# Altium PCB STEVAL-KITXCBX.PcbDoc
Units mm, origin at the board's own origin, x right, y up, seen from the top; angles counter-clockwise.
Board outline 62 x 54 mm, 2 copper layers (Top Layer, Bottom Layer), stack 1.543 mm thick; 46 components, 22 nets, 135 pads, 31 vias.
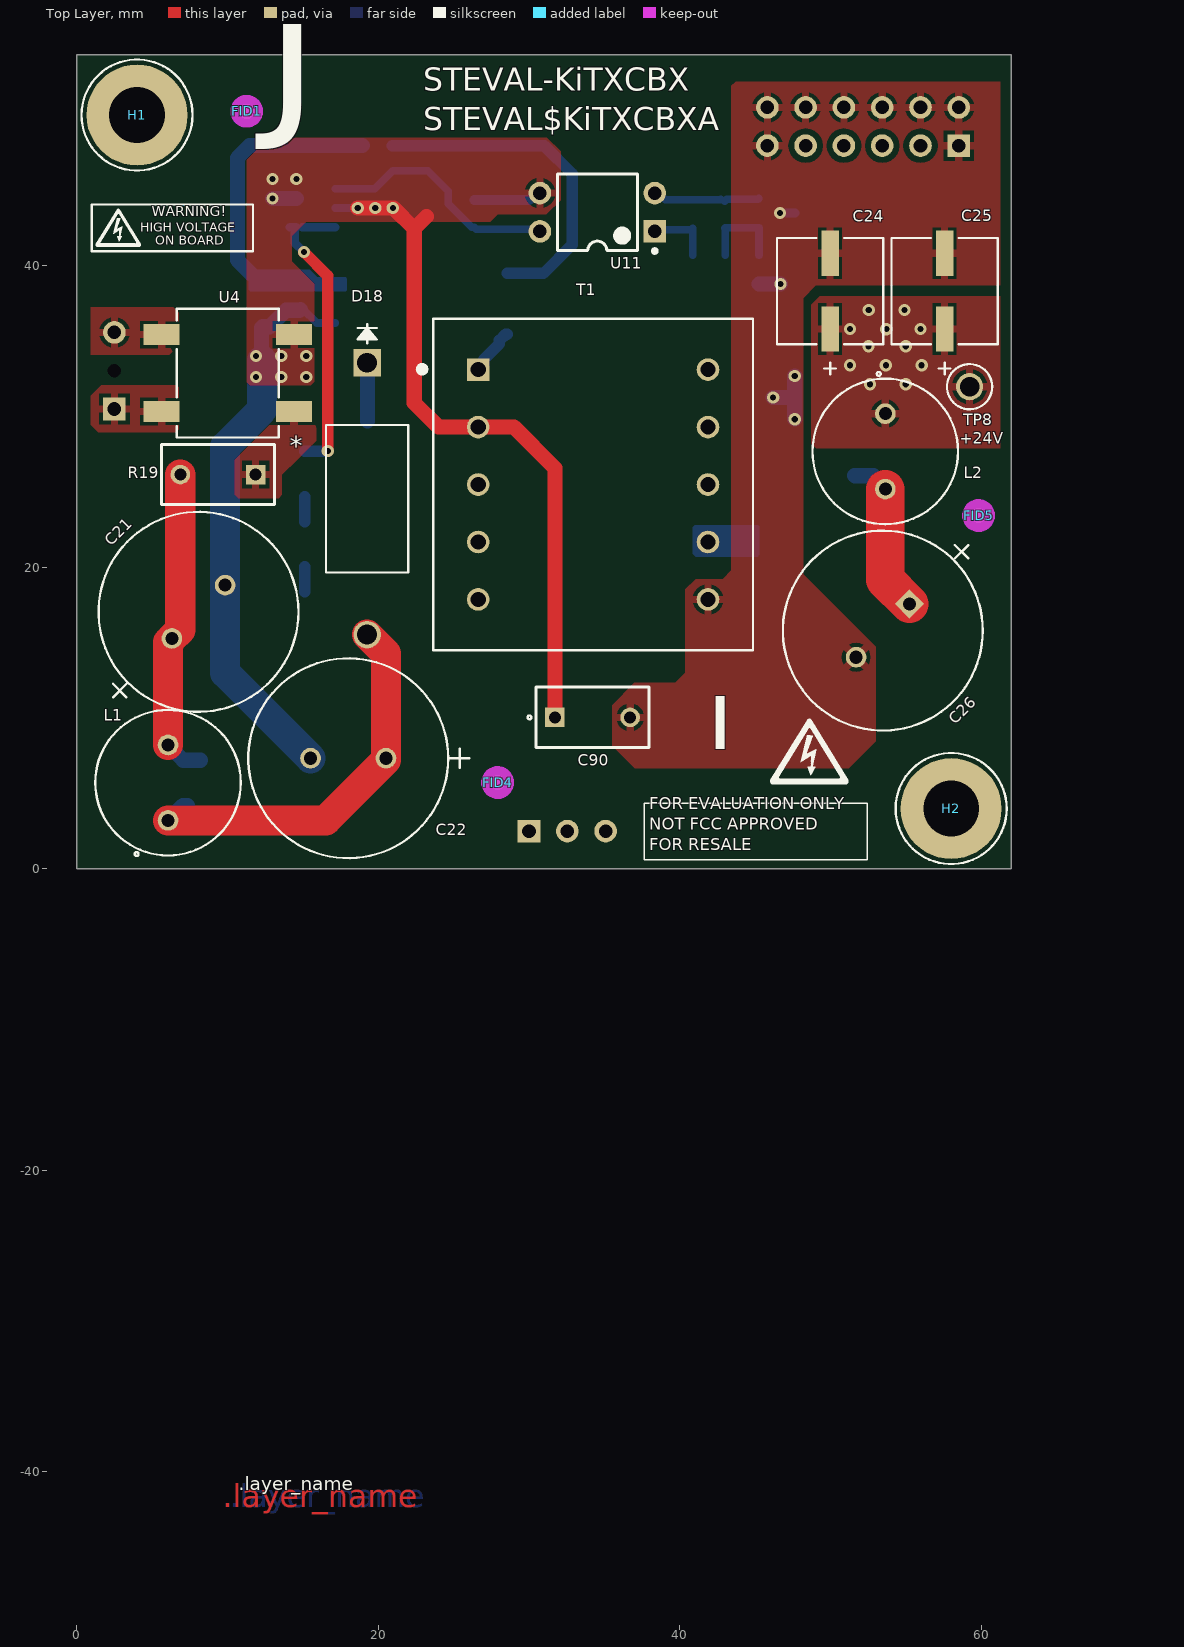
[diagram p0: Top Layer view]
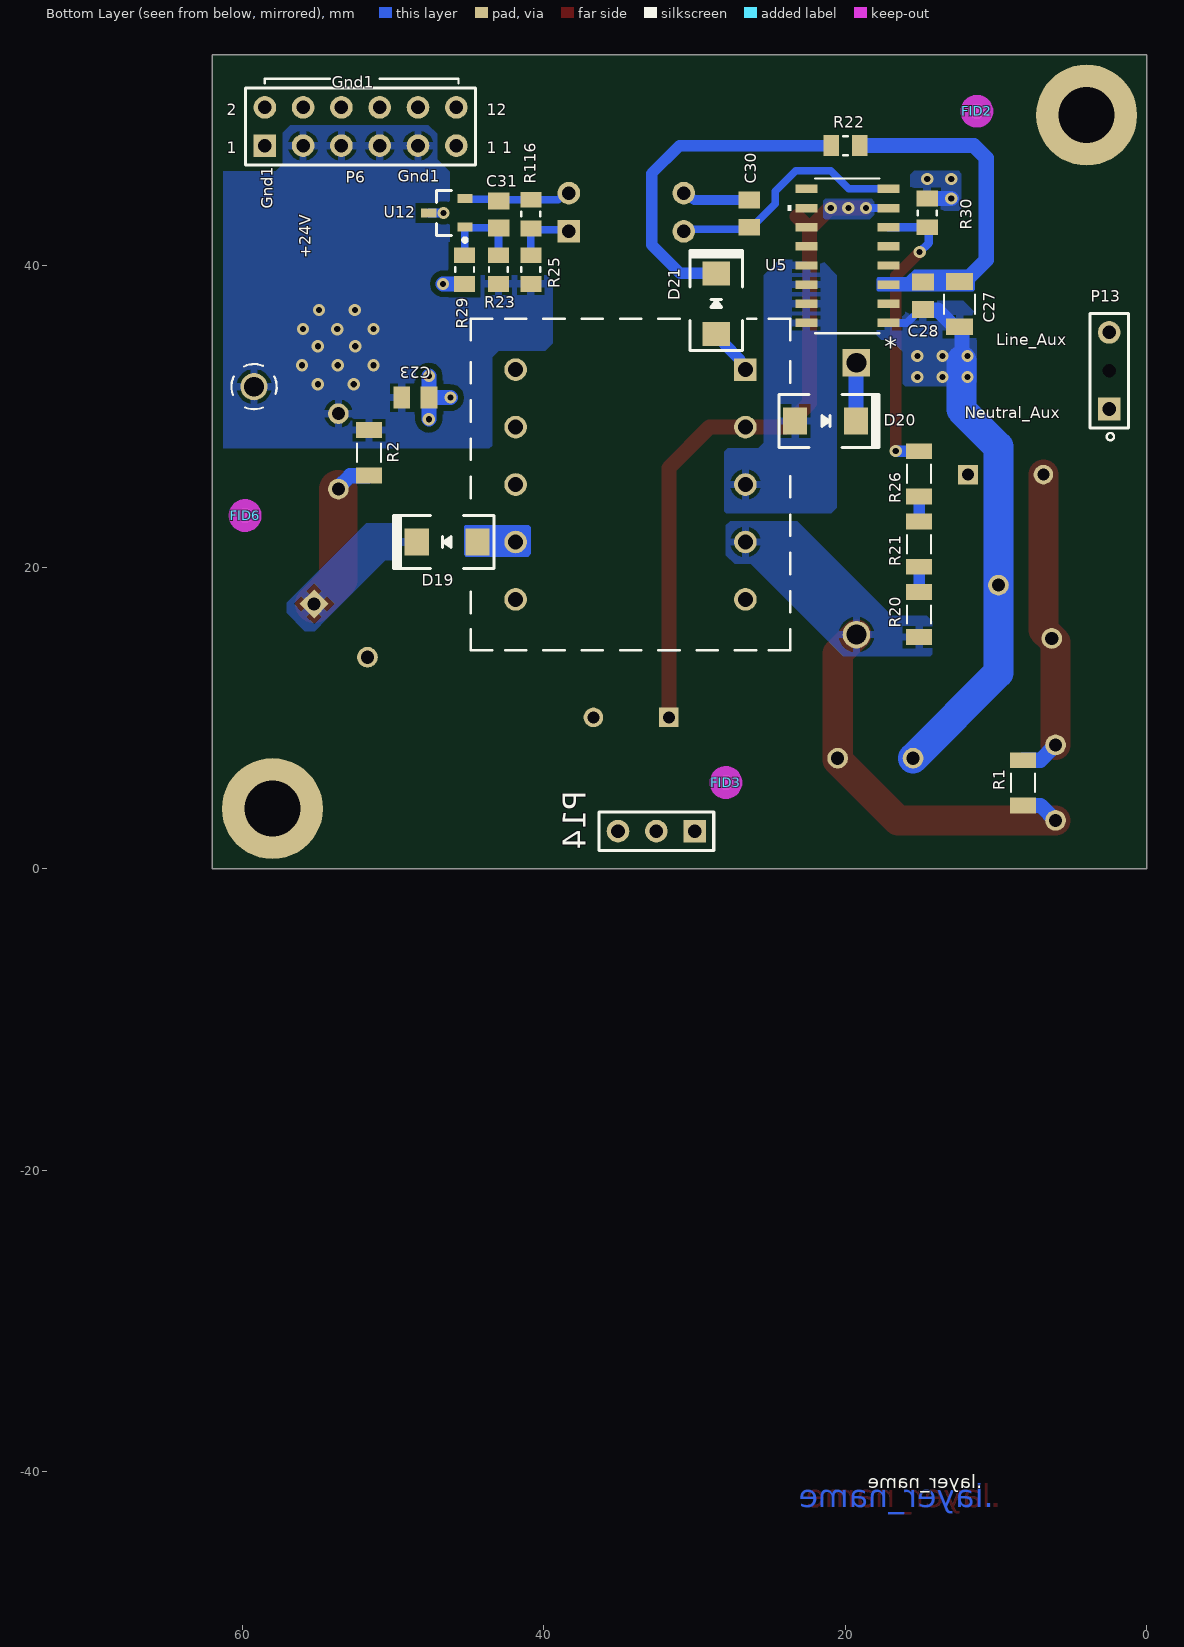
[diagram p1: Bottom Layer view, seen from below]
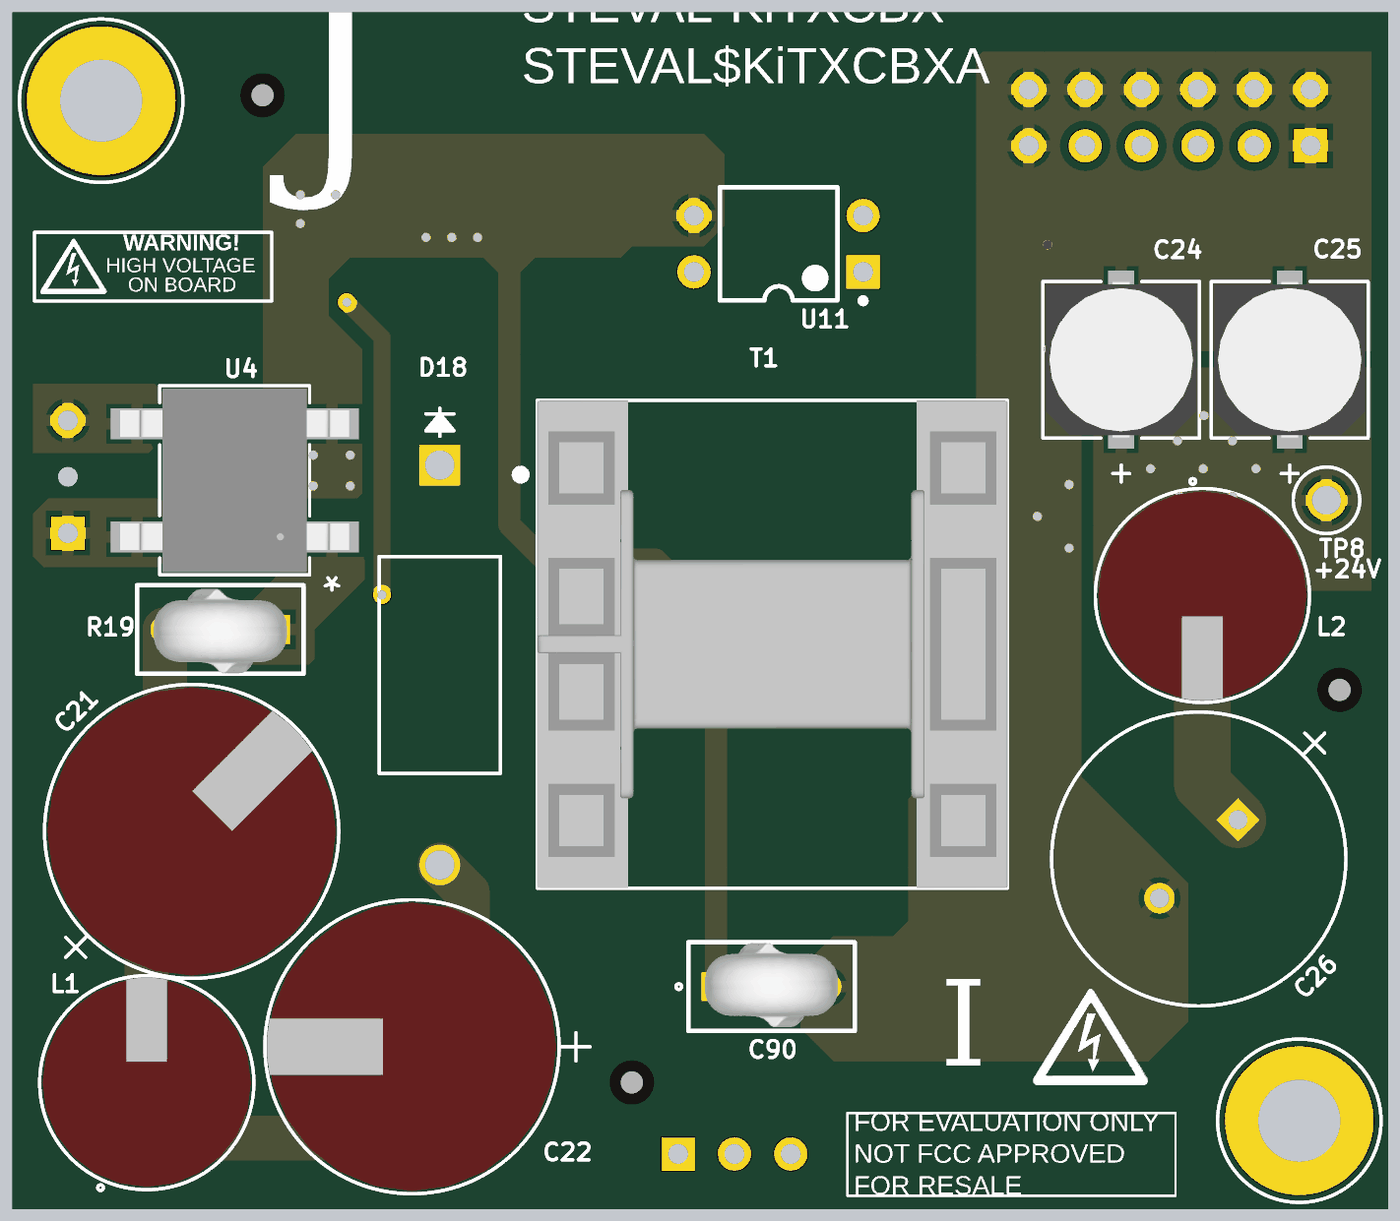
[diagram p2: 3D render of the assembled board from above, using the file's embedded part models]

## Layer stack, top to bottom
Top Solder: solder mask 0.0102, Solder Resist, Dk 3.5
Top Layer: signal copper 0.035
Dielectric: core 1.4732, FR-4 High TG, Dk 4.2
Bottom Layer: signal copper 0.035
Bottom Solder: solder mask 0.0102, Solder Resist, Dk 3.5

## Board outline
0,0 0,54 62,54 62,0

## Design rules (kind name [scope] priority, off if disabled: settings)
AcuteAngle [All] p1: minimum=4.50000000000000E+0001 checktracksonly=FALSE
AssemblyTestPointUsage [All] p1: valid=2
BoardOutlineClearance BoardOutlineClearance_MountingHoles [OnCopper and InComponentClass('Mounting Holes')] p1: gap=1.016 ignorepadtopadclearanceinfootprint=FALSE
BoardOutlineClearance BoardOutlineClearance_Poly [OnCopper and IsPoly] p2: gap=0.737 ignorepadtopadclearanceinfootprint=FALSE
BoardOutlineClearance [OnCopper and Not InComponentClass('Logo') and not InComponentClass('FiducialMark') and not InRegion(1000,500,4000,800) and not InPoly] p3: gap=0.737 ignorepadtopadclearanceinfootprint=FALSE except(0: Text-OutlineEdge; 0.635: SMDPad-OutlineEdge THPad-OutlineEdge)
Clearance Clearance_Keepouts [((IsTrack Or IsArc) And Not InPoly) And IsFree and IsKeepOut vs ((IsTrack Or IsArc) And Not InPoly) And IsFree and IsKeepOut] p1: gap=0 ignorepadtopadclearanceinfootprint=FALSE
Clearance Clearance_FiducialMark [IsKeepOut and InComponentClass('FiducialMark') vs IsPad and InComponentClass('FiducialMark')] p2: gap=0 ignorepadtopadclearanceinfootprint=FALSE
Clearance [All] p3: gap=0.229 ignorepadtopadclearanceinfootprint=TRUE except(0: Arc-SMDPad; 0.381: Arc-Poly Track-Poly SMDPad-Poly THPad-Poly Via-Poly Fill-Poly Fill-Region Poly-Region Region-Region; 0.508: Poly-Poly)
DiffPairsRouting [All] p1: maxlimit=2.54 minlimit=0.254 mostfreqgap=0.254 toplayer_minwidth=0.381 toplayer_maxwidth=0.381 toplayer_prefwidth=0.381 bottomlayer_minwidth=0.381 bottomlayer_maxwidth=0.381 bottomlayer_prefwidth=0.381 maxuncoupledlength=25.4
FabricationTestPointUsage TestPointUsage [All] p1: valid=2 allowmultiple=FALSE
FabricationTestpoint Testpoint [All] p1: side=3 testpointundercomponent=TRUE minsize=1.016 maxsize=2.54 preferedsize=1.524 minholesize=0 maxholesize=1.016 preferedholesize=0.813 testpointgrid=0.025 allowsidetop=TRUE allowsidebottom=TRUE usegrid=TRUE gridtolerance=0
FanoutControl Fanout_LCC [IsLCC] p1: bgadir=Out bgaviamode=Centered fanoutstyle=Auto fanoutdirection=Alternating viagrid=0.025 // Fanout_LCC (Default Rule)
FanoutControl Fanout_BGA [IsBGA] p2: bgadir=Out bgaviamode=Centered fanoutstyle=Auto fanoutdirection=Alternating viagrid=0.025 // Fanout_BGA (Default Rule)
FanoutControl Fanout_Default [All] p4: bgadir=Out bgaviamode=Centered fanoutstyle=Auto fanoutdirection=Alternating viagrid=0.025 // Fanout_Default (Default Rule)
FanoutControl Fanout_Small [(CompPinCount < 5)] p5: bgadir=Out bgaviamode=Centered fanoutstyle=Auto fanoutdirection=OutThenIn viagrid=0.025 // Fanout_Small (Default Rule)
HoleSize [All] p1: absolutevalues=TRUE maxlimit=6.375 minlimit=0.2 maxpercent=80.000 minpercent=20.000
HoleToHoleClearance [All] p1: gap=0.2 allowstackedmicrovias=TRUE
MinimumAnnularRing MinimumAnnularRing_ThermalPadVias [IsVia and InAnyComponent] p1: minimumring=0.15
MinimumAnnularRing [All] p2: minimumring=0.127
MinimumSolderMaskSliver MinimumSolderMaskSliver_Logo [InComponentClass('Logo') vs InComponentClass('Logo')] p1: minsoldermaskwidth=0.018
MinimumSolderMaskSliver [All] p2: minsoldermaskwidth=0.076
PlaneConnect [All] p1: planeconnectstyle=Relief reliefexpansion=0.254 reliefentries=4 reliefconductorwidth=0.254 reliefairgap=0.254
PolygonConnect [All] p1: thpad.connectstyle=Relief thpad.reliefconductorwidth=0.508 thpad.reliefentries=4 thpad.polygonreliefangle="90 Angle" thpad.airgapwidth=0.254 smdpad.connectstyle=Relief smdpad.reliefconductorwidth=0.508 smdpad.reliefentries=4 smdpad.polygonreliefangle="90 Angle" smdpad.airgapwidth=0.2 via.connectstyle=Direct via.reliefconductorwidth=0.254 via.reliefentries=4 via.polygonreliefangle="90 Angle" via.airgapwidth=0.254
RoutingVias ThermalPadVias [IsVia and InAnyComponent] p1: holewidth=0.2 width=0.5 viastyle="Through Hole" minholewidth=0.2 minwidth=0.5 maxholewidth=0.33 maxwidth=0.6
RoutingVias [All] p2: holewidth=0.305 width=0.61 viastyle="Through Hole" minholewidth=0.406 minwidth=0.813 maxholewidth=0.406 maxwidth=0.914
SilkToBoardRegionClearance [Not ((IsComment or IsDesignator) And (Hide <> 'False')) and not InRegion(1000,500,4000,800)] p1:
SilkToSilkClearance SilkToSilkClearance_Pb-FreeLogo [(HasFootprint('Pb-Free_Overlay_Medium') OR HasFootprint('Pb-Free_Overlay_Small')) vs (HasFootprint('Pb-Free_Overlay_Medium') OR HasFootprint('Pb-Free_Overlay_Small'))] p1: silktosilkclearance=0
SilkToSilkClearance [All] p2: silktosilkclearance=0.003
SilkToSolderMaskClearance SilkToComponentPadClearance [(IsPad or IsFill or IsRegion) and InAnycomponent] p1: minsilkscreentomaskgap=0.025 clearancetoexposedcopper=TRUE
SilkToSolderMaskClearance "Silk to Solder Mask Opening" [All] p2: minsilkscreentomaskgap=0 clearancetoexposedcopper=FALSE
SolderMaskExpansion [All] p1: expansion=0.05 istentingtop=FALSE
UnRoutedNet [All] p1: checkbadconnections=TRUE
Width [All] p1: maxlimit=2.54 minlimit=0.152 preferedwidth=0.254 checkconnectedcopper=TRUE
14 further rules are at their usual default settings.

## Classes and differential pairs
component class "D-Aux. Power Supply": C21 C22 C23 C24 C25 C26 C27 C28 C30 C31 C90 CR1 D19 D20 D21 H1 H2 L1 L2 P6 P13 P14 R1 R2 R19 R20 R21 R22 R23 R25 R26 R29 R30 R116 T1 TP8 U4 U5 U11 U12

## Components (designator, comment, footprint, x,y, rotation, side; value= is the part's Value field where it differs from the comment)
C21 "22µF/450 V" CAP_BX_12P5x20_RUB 6.31,15.281 r45 top
C22 "22µF/450 V" CAP_BX_12P5x20_RUB 20.508,7.337 r180 top
C23 "100nF" CAP_0805J_AVX 48.525,31.258 r0 bottom
C24 "22uF" PCAP_EEHZ_D_PAN 49.973,38.319 r90 top
C25 "22uF" PCAP_EEHZ_D_PAN 57.567,38.319 r90 top
C26 "220uF" CAP_2135_12.5X20_VIS 55.235,17.572 r225 top
C27 "10uF/50V" CAP_X7R_1206_AVX 12.431,37.455 r90 bottom
C28 "100nF" CAP_0805J_AVX 14.844,38.014 r90 bottom
C30 "1nF" CAP_0805J_AVX 26.376,43.462 r270 bottom
C31 "47nF" CAP_0805J_AVX 42.992,43.399 r270 bottom
C90 "1nF" Vishay_S102K29Y5PN6TJ5R_0 34.21,10.048 r0 top
D18 "1.5KE300A" DO-201_DIO 19.264,33.569 r270 top
D19 "STTH1R02A" DO214AC-SMA 46.417,21.682 r0 bottom
D20 "STTH1L06A" DO214AC-SMA 21.313,29.708 r180 bottom
D21 "STPS1L60A" DO214AC-SMA 28.56,37.48 r90 bottom
FID1 "Fiducial" Fiducial10-20 11.276,50.248 r0 top
FID2 "Fiducial" Fiducial10-20 11.276,50.248 r180 bottom
FID3 "Fiducial" Fiducial10-20 27.918,5.726 r180 bottom
FID4 "Fiducial" Fiducial10-20 27.918,5.726 r0 top
FID5 "Fiducial" Fiducial10-20 59.815,23.432 r0 top
FID6 "Fiducial" Fiducial10-20 59.815,23.432 r180 bottom
H1 "Hole" HOLE_M3#1 4,50 r0 top
H2 "Hole" HOLE_M3#2 58,4 r0 top
L1 "RLB0914-102KL" IND_RFB0810 6.056,3.216 r90 top
L2 "2.2uH" IND_RFB0810 53.63,30.191 r270 top
P6 "SSW-106-01-G-D" HDR2X6 58.507,47.968 r180 bottom
P13 "SSW-103-01-G-S" HDR1X3#1 2.5,30.5 r90 bottom
P14 "SSW-103-01-G-S" HDR1X3#2 30,2.5 r0 bottom
R1 "NM" RC1206 8.215,5.705 r270 bottom
R2 "NM" RC1206 51.598,27.598 r90 bottom
R19 "B57153S0479M000" R? 11.869,26.152 r180 top
R20 "2M" RC1206 15.115,16.872 r270 bottom
R21 "2M" RC1206 15.115,21.534 r270 bottom
R22 "10" RC0805 19.99,47.968 r0 bottom
R23 "220k" RC0805 43.018,39.75 r270 bottom
R25 "390" RC0805 40.864,39.75 r270 bottom
R26 "2M" RC1206 15.115,26.196 r270 bottom
R29 "12k" RC0805 45.255,39.75 r90 bottom
R30 "62k" RC0805 14.565,43.51 r270 bottom
R116 "1.8k" RC0805 40.864,43.434 r270 bottom
T1 "AD1914-AL" TDK_B66206B1110T001 34.25,25.492 r0 top
TP8 "+24V" TP_20-2136 59.223,31.982 r180 top value="Test Point"
U4 "DF08S-E3/77" SO4_DFS_VIS 10.018,32.883 r180 top
U5 "VIPER318LDTR" SO_18HDTR_STM 19.867,40.655 r0 bottom
U11 "SFH610A-4" DIP-4 34.529,43.551 r180 top
U12 "TS3431BILT" SOT95P245X112-3N 46.433,43.51 r0 bottom

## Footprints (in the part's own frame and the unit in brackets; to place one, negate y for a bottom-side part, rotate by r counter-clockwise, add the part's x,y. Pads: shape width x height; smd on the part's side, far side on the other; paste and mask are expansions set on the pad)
CAP_0805J_AVX [mil]
  rect 44x57 smd paste+0 mask+0: 1(-35.5,0) 2(35.5,0)
  body extent 0,0 10,10, height 10
CAP_2135_12.5X20_VIS [mil]
  rect 54x54 hole 34 mask+0: 1(0,0)
  round 54 hole 34 mask+0: 2(196.85,0)
  silkscreen extent -218,-261 359,261, body extent 0,0 10,10, height 10
CAP_BX_12P5x20_RUB [mil]
  round 54 hole 34 mask+0: 1(0,0) 2(196.85,0)
  silkscreen extent -218,-261 359,261, body extent -158,-256 356,256, height 867
CAP_X7R_1206_AVX [mil]
  rect 44x71 smd paste+0 mask+0: 1(-59,0) 2(59,0)
  silkscreen extent -25,-40 25,40, body extent 0,0 10,10, height 10
DIP-4 [mm] "DIP; 4 Leads; Row Spacing 7.62 mm; Pitch 2.54 mm"
  rect 1.5x1.5 hole 0.9: 1(-3.81,1.27)
  round 1.5 hole 0.9: 2(-3.81,-1.27) 3(3.81,-1.27) 4(3.81,1.27)
  silkscreen extent -3.93,-2.55 2.65,2.69, body extent -3.15,-2.5 3.15,2.5, height 5.6
DO214AC-SMA [mm]
  rect 1.6x1.8 smd paste+0 mask+0.102: 1(-2.015,0) 2(2.015,0)
  silkscreen extent -3.1,-1.75 3.55,1.75, body extent -2.58,-1.3 2.5,1.28, height 2.65
DO-201_DIO [mil]
  rect 72x72 hole 52 mask+0: 1(0,0)
  round 72 hole 52 mask+0: 2(710,0)
  silkscreen extent -101,-108 548,108, body extent 0,0 10,10, height 10
Fiducial10-20 [mm]
  round 1 smd mask+0.5: 1(0,0)
  Top Layer keep-out circle w1.178: c0,0 r0.5
HDR1X3#1 [mm] "Connector; Header; 3 Position"
  rect 1.5x1.5 hole 0.9: 1(0,0)
  round 0 hole 0.9 unplated mask+0.127: 2(2.54,0)
  round 1.5 hole 0.9: 3(5.08,0)
  silkscreen extent -1.27,-1.27 6.35,1.27
HDR1X3#2 [mm] "Connector; Header; 3 Position"
  rect 1.5x1.5 hole 0.9: 1(0,0)
  round 1.5 hole 0.9: 2(2.54,0) 3(5.08,0)
  silkscreen extent -1.27,-1.27 6.35,1.27
HDR2X6 [mm] "Connector; Header; 6x2 Position"
  rect 1.5x1.5 hole 0.9: 1(0,0)
  round 1.5 hole 0.9: 2(0,2.54) 3(2.54,0) 4(2.54,2.54) 5(5.08,0) 6(5.08,2.54) 7(7.62,0) 8(7.62,2.54) 9(10.16,0) 10(10.16,2.54) 11(12.7,0) 12(12.7,2.54)
  silkscreen extent -1.27,-1.27 13.97,3.81
HOLE_M3#1 [mm]
  round 0 all layers, no hole mask+0: 1(-2.25,0) 1(-1.125,-1.949) 1(-1.125,1.949) 1(1.125,-1.949) 1(1.125,1.949) 1(2.25,0)
  round 6.7 hole 3.7 mask+0.1: 1(0,0)
  silkscreen extent -3.68,-3.68 3.68,3.68
HOLE_M3#2 [mm]
  round 0 all layers, no hole: 1(-2.25,0) 1(-1.125,-1.949) 1(-1.125,1.949) 1(1.125,-1.949) 1(1.125,1.949) 1(2.25,0)
  round 6.7 hole 3.7: 1(0,0)
  silkscreen extent -3.68,-3.68 3.68,3.68
IND_RFB0810 [mil]
  round 54 hole 34 mask+0: 1(0,0) 2(197,0)
  silkscreen extent -92,-190 288,190, body extent -86,-185 285,185, height 451
PCAP_EEHZ_D_PAN [mil]
  rect 118x46 smd paste+0 mask+0: 1(-99,0) 2(99,0)
  silkscreen extent -217,-139 139,139, body extent -138,-134 138,134, height 242
R? [mm]
  rect 1.3x1.3 hole 0.8 paste-1000 mask+0: 1(0,0)
  round 1.3 hole 0.8 paste-1000 mask+0: 2(5,0)
  silkscreen extent -1.25,-2 6.25,2, body extent -1.35,-2.1 6.35,2.1, height 0.25
RC0805 [mm]
  rect 1.05x1.4 smd: 1(-0.95,0) 2(0.95,0)
  silkscreen extent -0.15,-0.63 0.15,0.63, body extent -1,-0.63 1,0.63, height 0.84
RC1206 [mm] "RES, SMD, 1.2K OHM,  5%, 1/4W, 1206"
  rect 1.05x1.75 smd: 1(-1.5,0) 2(1.5,0)
  silkscreen extent -0.6,-0.8 0.6,0.8, body extent -1.6,-0.8 1.6,0.8, height 0.84
SO4_DFS_VIS [mm]
  rect 2.4x1.4 smd paste+0 mask+0: 1(-4.394,2.55) 2(-4.394,-2.55) 3(4.394,-2.55) 4(4.394,2.55)
  silkscreen extent -3.38,-4.27 3.38,4.27, body extent -5.16,-4.14 5.16,4.14, height 2.92
SO_18HDTR_STM [mil]
  rect 57.55x22 smd paste+0 mask+0: 1(-107.27,175) 2(-107.27,125) 3(-107.27,75) 4(-107.27,25) 5(-107.27,-25) 6(-107.27,-75) 7(-107.27,-125) 8(-107.27,-175) 9(107.27,-175) 10(107.27,-125) 11(107.27,-75) 12(107.27,-25) 13(107.27,25) 14(107.27,75) 15(107.27,125) 16(107.27,175)
  silkscreen extent -84,-202 156,202, body extent 0,0 10,10, height 10
SOT95P245X112-3N [mm] "SOT23, 3-Leads, Body 2.92x2.45mm, Pitch 0.95mm, IPC Medium Density"
  rect 1x0.6 smd: 1(-1.2,0.95) 2(-1.2,-0.95) 3(1.2,0)
  silkscreen extent -1.32,-1.5 0.7,1.92, body extent -1.3,-1.52 1.3,1.52, height 1.12
TDK_B66206B1110T001 [mm] "BOBBIN COIL FORMER, E 20/10/6 , 10 POS, TH"
  rect 1.5x1.5 / inner round 1.5 / far side rect 1.5x1.5 hole 1: 1(-7.62,7.62)
  round 1.5 hole 1: 2(-7.62,3.81) 3(-7.62,0) 4(-7.62,-3.81) 5(-7.62,-7.62) 6(7.62,-7.62) 7(7.62,-3.81) 8(7.62,0) 9(7.62,3.81) 10(7.62,7.62)
  silkscreen extent -11.75,-11 10.6,11, body extent -10.6,-11 10.6,11, height 16.65
TP_20-2136 [mm] "TEST POINT, BLACK, TH"
  round 1.8 hole 1.3: 1(0,0)
  silkscreen extent -1.5,-1.5 1.5,1.5, body extent -1.49,-1.5 1.5,1.5, height 5.4
Vishay_S102K29Y5PN6TJ5R_0 [mm]
  rect 1.3x1.3 hole 0.8 paste-1000 mask+0: 1(-2.5,0)
  round 1.3 hole 0.8 paste-1000 mask+0: 2(2.5,0)
  silkscreen extent -3.75,-2 3.75,2, body extent -3.85,-2.1 3.85,2.1, height 0.25

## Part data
C21 C22: library part 450BXF22M12.5X20, "22 µF 450 V Aluminum Electrolytic Capacitors Radial, Can - 10000 Hrs @ 105°C", Manufacturer_Part_Number=EKXN451ELL220MK16S, Mfr_Name=Rubycon
C23 C28 C30 C31: library part 08051A561JAT2A, "No Description Available"
C24: library part EEHZA1H220P, "Cap Aluminum 22uF 50V 20% (6.3 X 5.8mm) SMD 0.08 Ohm 1100mA 5000 hr 105°C Embossed T/R", Manufacturer_Part_Number=50PEV22M6.3X6.1, Mfr_Name=Rubycon
C25: library part EEHZA1H220P, "No Description Available", Manufacturer_Part_Number=50PEV22M6.3X6.1, Mfr_Name=Rubycon
C26: library part MAL213668221E3, "No Description Available", Manufacturer_Part_Number=URZ1J221MHD1TO, Mfr_Name=Vishay
C27: library part 12061C104KAT2A, "No Description Available"
C90: library part S102K29Y5PN6TJ5R, "Cap Ceramic 0.001uF 1000V Y5P 10% (7.5 X 4mm) Radial 5mm 85°C T/R", Supplier Part Number 1=810-CK45-B3AD102KYVN
D18: library part 1.5KE300A-T, "Transient Voltage Suppressor diode, D5.4x7.5, 285.00V .. 315.00V, 1500W", Manufacturer 1=STMicroelectronics, Supplier Part Number 1=9884947
D19: library part "Diode Schottky STPS1150A", "Schottky Rectifier Diode", Average Rectified Current=1A, Case/Package=SMA, Forward Voltage=890mV, Manufacturer 2=STMicroelectronics, Manufacturer Part Number 2=STPS1150A, Max Forward Surge Current (Ifsm)=50A, Max Operating Temperature=175°C, Max Repetitive Reverse Voltage (Vrrm)=150V, Max Reverse Current=1uA, Min Operating Temperature=-65°C, Package Quantity=1, Peak Non-Repetitive Surge Current=75A
D20: library part "Diode STH1L06A", "Diode", Average Rectified Current=1A, Case/Package=SMA, Forward Voltage=1.3V, Manufacturer 1=STMicroelectronics, Max Forward Surge Current (Ifsm)=10A, Max Operating Temperature=175°C, Max Repetitive Reverse Voltage (Vrrm)=600V, Max Reverse Current=1uA, Max Surge Current=20A, Min Operating Temperature=-65°C, Package Quantity=1, Supplier Part Number 1=8165505
D21: library part "Diode STPS1L30A", "Small Signal Schottky Diode", Average Rectified Current=1A, Case/Package=SMA, Forward Voltage=395mV, Manufacturer 2=STMicroelectronics, Manufacturer Part Number 2=STPS1L30A, Max Forward Surge Current (Ifsm)=75A, Max Operating Temperature=150°C, Max Repetitive Reverse Voltage (Vrrm)=30V, Max Reverse Current=200uA, Min Operating Temperature=-65°C, Package Quantity=1, Supplier Part Number 1=9907491
FID1 FID2 FID3 FID4 FID5 FID6: library part CMP-0077181-1, "Fiducial mark.  There is nothing to buy or mount.", Manufacturer=N/A
L1: library part RFB0810-330L, "No Description Available", Mfr_Name=Coilcraft
L2: library part RFB0810-330L, "Inductor, Fixed, Power, Ferrite Core, 2.2uH, 2.6A, 29mohm", Manufacturer 1=KEMET, Manufacturer Part Number 1=SBCP-47HY2R2B, Supplier Part Number 1=3011785
P6: library part "Header 6X2", "connector, 6-Pin, Dual row"
P13 P14: library part "Header 3", "connector, 3-Pin"
R1 R2 R20 R21 R26: library part RESISTOR, "RESISTOR 1206"
R19: library part RESISTOR, "Inrush Current Limiter 4.7 Ohms ±20% 3 A"
R22 R23 R25 R29 R30 R116: library part RESISTOR, "RESISTOR 0805"
T1: library part B66206B1110T001, "Coil Craft Transformer", Manufacturer="Coil Craft", Operating_Temp="+155C MAX"
TP8: library part TESTP, "Test Point", Colour=Black, Supplier Part Number 1=8731195
U4: "No Description Available", Mfr_Name=Vishay
U5: library part VIPER318HDTR, "No Description Available"
U11: library part Optoisolator1, "4-Pin Phototransistor Optocoupler"
U12: "1.24V Programmable Shunt Voltage Reference", Package=None

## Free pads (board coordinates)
  round 0.508 on Mech11: 1(70.728,-47.795)

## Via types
v1: diameter 0.813, hole 0.406, Top Layer to Bottom Layer, tented both sides, 29 vias
v2: diameter 0.813, hole 0.406, Top Layer to Bottom Layer, 2 vias

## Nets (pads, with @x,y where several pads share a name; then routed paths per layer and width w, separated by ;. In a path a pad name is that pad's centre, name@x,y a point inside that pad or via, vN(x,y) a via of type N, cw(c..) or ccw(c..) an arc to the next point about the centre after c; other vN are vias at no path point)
+24V: C23.2 C24.1 C25.1 L2.1 P6.3 P6.5 P6.7 P6.9 R2.2 R23.2 R25.2 TP8.1
  other v1: 52.613,32.146 54.988,32.146 51.293,33.404 53.669,33.404 56.045,33.404 52.511,34.661 54.988,34.661 53.7,35.8 51.293,35.804 55.967,35.804 52.535,37.061 54.91,37.061
GND: C21.2 C22.2 C27.1 C28.1 C30.1 C90.1 R30.1 T1.2 U4.2 U5.1 U5.7 U11.3 | length 89.1
  Top Layer w1: v1@18.639,43.83 21.017,43.83 22.388,42.459 ; 23.214,43.284 22.388,42.459 ; C90.1 31.71,26.597 29.005,29.302 T1.2 23.988,29.302 22.388,30.902 22.388,42.459
  Bottom Layer w0.508: C28.1 15.01,37.112 15.911,36.21 U5.1 ; U5.7 v1@18.639,43.83
  Bottom Layer w0.635: C30.1 30.028,44.364 30.485,44.821 U11.3
  Bottom Layer w1: 12.254,34.585 12.254,35.898 12.312,35.956 C27.1 12.774,35.956 13.871,37.053 14.786,37.053 C28.1 ; v1(12.978,44.46) R30.1
  Bottom Layer w2: 12.3,33.7 12.3,30.467 9.846,28.012 C21.2 9.846,13 C22.2
  other v1: 11.898,32.629 13.562,32.629 15.225,32.629 11.898,34.02 13.562,34.02 15.225,34.02 18.639,43.835 19.802,43.835 20.966,43.835 12.978,45.761 14.565,45.761
Gnd1: C23.1 C24.2 C25.2 C26.2 C90.2 P6.1 P6.2 P6.4 P6.6 P6.8 P6.10 P6.11 P6.12 R29.1 T1.6 U12.3 | length 6.7
  Bottom Layer w0.6: v1(46.654,43.51) U12.3
  Bottom Layer w1: R29.1 v1(46.686,38.8) ; v1(46.192,31.258) C23.1 ; v1(47.623,32.689) C23.1 ; v1(47.625,29.825) 47.625,31.256 C23.1
NetC21_1: C21.1 L1.2 R1.1 R19.2 | length 21
  Top Layer w2: L1.2 6.056,15.027 C21.1 6.869,15.84 R19.2
  Bottom Layer w1: L1.2@6.127,8.149 L1.2 6.056,8.214 7.065,7.205 R1.1
NetC22_1: C22.1 D18.2 L1.1 R1.2 R20.2 T1.4 | length 26.7
  Top Layer w2: L1.1 16.514,3.216 20.508,7.21 20.508,14.291 D18.2
  Bottom Layer w1: L1.1 7.045,4.205 R1.2@7.35,4.205
NetC26_1: C26.1 D19.2 L2.2 R2.1 | length 10.7
  Top Layer w2.54: L2.2 53.63,19.177 C26.1
  Bottom Layer w1: R2.1 51.623,26.073 52.844,26.073 53.63,25.287 L2.2
NetC30_2: C30.2 U5.8 U11.4 | length 16.2
  Bottom Layer w0.508: U5.8 19.772,45.1 20.966,46.294 23.287,46.294 24.644,44.938 24.644,44.128 26.211,42.56 C30.2 26.516,42.421 30.58,42.421 U11.4
NetC31_1: C31.1 R116.1 U11.2 U12.2 | length 6.9
  Bottom Layer w0.508: U11.2 38.608,44.821 39.045,44.384 R116.1 42.683,44.384 C31.1@42.721,44.422 ; C31.1 43.106,44.414 45.187,44.414 U12.2
NetC31_2: C31.2 R23.1 R29.2 U12.1 | length 5.9
  Bottom Layer w0.508: R23.1 43.005,40.713 43.005,42.484 C31.2 43.023,42.529 U12.1@45.131,42.529 ; U12.1@45.131,42.514 45.255,42.514 R29.2
NetD18_1: D18.1 D20.2 | length 3.9
  Bottom Layer w1: D18.1 19.281,33.552 19.281,29.725 D20.2
NetD19_1: D19.1 T1.7
NetD20_1: D20.1 T1.3 U5.13 U5.14 U5.15 U5.16
NetD21_1: D21.1 T1.1 | length 3.2
  Bottom Layer w0.762: T1.1 26.999,33.481 26.999,33.785 28.041,34.828 28.041,35.046 28.46,35.465 D21.1
NetD21_2: D21.2 R22.2 | length 22.5
  Bottom Layer w0.762: R22.2 31.002,47.968 32.853,46.116 32.853,41.392 30.956,39.495 D21.2
NetR19_1: R19.1 U4.1
NetR20_1: R20.1 R21.2 | length 1.7
  Bottom Layer w0.762: R20.1 R21.2
NetR21_1: R21.1 R26.2 | length 1.7
  Bottom Layer w0.762: R21.1 R26.2
NetR25_1: R25.1 R116.2 U11.1 | length 4.4
  Bottom Layer w0.508: U11.1 38.441,42.383 R116.2@40.864,42.383 ; R25.1 R116.2@40.864,42.383 ; R116.2 R116.2@40.864,42.383
VIPer_OVP: R26.1 R30.2 U5.6 | length 20
  Top Layer w0.762: v2(15.073,40.909) 16.658,39.324 v2(16.658,27.712)
  Bottom Layer w0.559: R30.2@14.143,42.56 R30.2 14.458,42.453 14.458,41.525 v2(15.073,40.909) ; R30.2@14.965,42.56 U5.6
  Bottom Layer w0.762: R26.1 15.122,27.704 16.65,27.704 v2(16.658,27.712)
VIPer_Vcc: C27.2 C28.2 R22.1 U5.3 | length 17.8
  Bottom Layer w1: C27.2 12.373,39.012 12.03,39.012 11.847,39.195 10.653,40.389 10.653,47.158 11.463,47.968 R22.1@18.937,47.968
~Line_Aux: P13.3 U4.3
~Neutral_Aux: P13.1 U4.4
pads on no net: FID1.1 FID2.1 FID3.1 FID4.1 FID5.1 FID6.1 H1.1 H2.1 P13.2 P14.1 P14.2 P14.3 T1.5 T1.8 T1.9 T1.10 U5.2 U5.4 U5.5 U5.9 U5.10 U5.11 U5.12

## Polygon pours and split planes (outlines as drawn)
Gnd1 on Top Layer "Top Layer-Gnd1" (solid, remove dead copper, pour order 37): 62,38.7 62,52.212 43.7,52.212 43.428,51.94 43.428,37.371 43.428,19.808 42.837,19.218 41.057,19.218 40.371,18.532 40.371,13.008 39.698,12.334 36.996,12.334 35.52,10.858 35.52,8.169 37.019,6.67 51.217,6.67 52.995,8.448 52.995,14.722 48.182,19.535 48.182,37.852 49.03,38.7
+24V on Top Layer "TOP_LAYER_+24V_P028" (solid, remove dead copper, pour order 28): 49.281,37.98 48.725,37.425 48.725,28.212 49.046,27.892 62,27.892 62,37.762 61.781,37.98
GND on Top Layer "TOP_LAYER_GND_P030" (solid, remove dead copper, pour order 30): 11.288,32.273 11.492,32.07 15.53,32.07 15.759,32.299 15.759,38.801 14.26,40.3 14.26,41.951 15.225,42.916 27.417,42.916 27.925,43.424 31.151,43.424 32.091,44.364 32.091,47.59 31.177,48.504 12.762,48.504 11.288,47.031
NetR19_1 on Top Layer "TOP_LAYER_NETR19_1_P026" (solid, remove dead copper, pour order 26): 13.39,24.577 13.615,24.802 13.615,26.145 15.911,28.431 15.911,30.8 15.761,30.95 13.222,30.956 12.965,30.699 12.965,29.632 10.476,27.143 10.476,24.806 10.704,24.577
~Line_Aux on Top Layer "TOP_LAYER_~LINE_AUX_P034" (solid, remove dead copper, pour order 34): 0.926,37.239 0.926,34.102 6.152,34.102 6.767,34.717 6.767,36.876 6.404,37.239
~Neutral_Aux on Top Layer "TOP_LAYER_~NEUTRAL_AUX_P033" (solid, remove dead copper, pour order 33): 1.418,28.961 0.926,29.454 0.926,31.372 1.624,32.07 6.64,32.07 6.767,31.943 6.767,29.124 6.605,28.961
+24V on Bottom Layer "TOP_LAYER_NONET_P-001" (solid, pour order 42): 47.652,49.325 56.822,49.325 57.325,48.822 57.325,46.747 57.791,46.282 61.8,46.282 62,46.082 62,28.515 61.376,27.892 43.608,27.892 43.428,28.072 43.428,33.94 42.988,34.38 39.909,34.38 39.425,34.864 39.425,38.947 39.837,39.358 45.81,39.358 46.235,39.783 46.235,46.234 47.075,47.075 47.075,48.748
GND on Bottom Layer "BOTTOM_LAYER_GND_P040" (solid, remove dead copper, pour order 40): 12.49,46.294 12.312,46.116 12.312,43.83 12.49,43.653 15.373,43.653 15.932,43.094 21.372,43.094 21.563,43.284 21.563,44.219 21.321,44.46 16.323,44.46 15.702,45.081 15.702,46.034 15.441,46.294
NetC22_1 on Bottom Layer "BOTTOM_LAYER_NETC22_1_P038" (solid, remove dead copper, pour order 38): 18.038,14.093 14.381,14.093 14.245,14.229 14.245,16.439 14.611,16.805 16.932,16.805 23.333,23.206 27.506,23.206 27.918,22.794 27.918,20.811 27.341,20.234 26.274,20.234 20.134,14.093
NetC26_1 on Bottom Layer "BOTTOM_LAYER_NETC26_1_P039" (solid, remove dead copper, pour order 39): 54.392,16.586 55.209,15.77 55.846,15.77 57.067,16.99 57.067,17.653 51.794,22.926 47.961,22.926 47.633,22.598 47.633,20.713 47.89,20.456 50.522,20.456
GND on Bottom Layer "BOTTOM_LAYER_GND_P029" (solid, remove dead copper, pour order 29): 17.003,35.093 16.208,34.297 16.208,32.184 16.03,32.007 11.555,32.007 11.3,32.262 11.3,36.794 12.177,37.671 15.539,37.671 16.03,37.18 16.03,36.82 16.208,36.642 17.765,36.642 17.926,36.482 17.926,35.398 17.621,35.093
NetD20_1 on Bottom Layer "BOTTOM_LAYER_NETD20_1_P025" (solid, remove dead copper, pour order 25): 21.563,40.389 20.559,39.385 20.559,23.968 20.94,23.587 27.9,23.587 28.027,23.714 28.027,27.651 27.786,27.892 25.779,27.892 25.411,28.26 25.411,39.373 24.395,40.389

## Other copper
Top Layer:
  pour cut-out: 1.382,26.762 8.875,26.762 11.06,28.946 11.06,44.745 10.679,45.126 8.532,45.126 8.253,44.846 8.253,29.838 7.377,28.961 1.76,28.961 1.23,28.431 1.23,26.914
  text ".layer_name" at 9.677,-42.342 h1.52
Bottom Layer:
  region net NetD19_1: 45.201,22.794 40.997,22.794 40.864,22.661 40.864,20.884 41.046,20.702 45.166,20.702 45.281,20.818 45.281,22.714
  region net VIPer_Vcc: 17.926,39.156 17.926,38.378 17.86,38.312 11.513,38.312 11.415,38.41 11.415,39.65 11.519,39.754 15.441,39.754 15.962,39.233 17.849,39.233
  text ".layer_name" at 10.16,-42.342 h1.52

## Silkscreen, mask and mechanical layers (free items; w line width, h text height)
Top Overlay:
  drawing of 15 lines, arcs and shapes, not listed
  text "STEVAL-KiTXCBX / STEVAL$KiTXCBXA" at 23,48.5 h2.6
  text "J" at 12.5,47.3 h15.24
  text "WARNING!" at 4.992,43.047 h1.16
  text "HIGH VOLTAGE" at 4.212,42.072 h1.04
  text "ON BOARD" at 5.206,41.206 h1.04
  text "+24V" at 58.583,28.198 h0.76
  text "I" at 41.8,6.5 h7.62
  text "FOR EVALUATION ONLY / NOT FCC APPROVED / FOR RESALE" at 37.973,0.955 h1.36
  text ".layer_name" at 10.744,-41.504 h1.52
Bottom Overlay:
  circle w0.152: c2.424,28.667 r0.244
  lines w0.152: 45.655,52.111 45.655,52.416 50.887,52.416 ; 54.189,52.416 58.507,52.416 58.507,52.111
  text "Gnd1" at 54.062,51.806 h0.76
  text "Gnd1" at 49.679,45.576 h0.76
  text "Gnd1" at 57.992,43.794 h0.76 r270
  text "+24V" at 55.459,40.503 h0.76 r270
  text "Line_Aux" at 9.993,34.737 h0.76
  text "Neutral_Aux" at 12.076,29.886 h0.76
  text ".layer_name" at 10.922,-41.377 h1.52
Top Paste:
  text ".layer_name" at 10.846,-41.478 h1.52
Bottom Paste:
  text ".layer_name" at 11.125,-41.352 h1.52
Top Solder:
  text ".layer_name" at 11.176,-41.478 h1.52
Bottom Solder:
  text ".layer_name" at 10.922,-41.427 h1.52
M1 Board Outline:
  the board outline again, w0.2
  text ".layer_name" at 10.864,-40.933 h1.52
M2 Board Dimensions:
  text ".layer_name" at 10.767,-41.36 h1.52
M3 3D STEP Top:
  text ".layer_name" at 11.278,-41.326 h1.52
M4 3D STEP Bottom:
  text ".layer_name" at 10.719,-41.325 h1.52
M5 Assembly Top:
  text ".layer_name" at 10.973,-40.851 h1.52
M6 Assembly Bottom:
  text ".layer_name" at 24.765,-41.199 h1.52
M9 Title Sheet:
  text ".layer_name" at 11.194,-41.124 h1.52
M10 Fab Notes:
  text "FAB NOTES:" at 66.445,10.275 h1.27
  text "1)ALL CORE AND PREPREG THICKNESSES ARE UP TO FAB SHOP TO SELECT." at 66.594,7.699 h1.27
  text "2)ALL VIAS ARE  NON TENTED" at 66.594,4.974 h1.27
  text "3)VENDOR MAY ADJUST SOLDERMASK WHEREVER SOLDERMASK PADS ARE SAME SIZE(1:1)" at 66.594,2.453 h1.27
  text "AS PER MANUFACTURING CAPABILITIES AND ALL OTHER SOLDERMASK PADS SHALL NOT BE MODIFIED" at 69.076,-0.417 h1.27
  text "PROVIDED NO ADJACENT COPPER IS EXPOSED AND NO CONFLICT PRODUCED WITH ANY STATED" at 69.076,-2.982 h1.27
  text "\"VIA TENTING/COVERING\" REQUIREMENTS." at 69.076,-5.345 h1.27
  text "4)THIS IS NOT AN IMPEDANCE CONTROLLED BOARD" at 66.569,-8.748 h1.27
  text "5)BOARD THICKNESS IS 1.6MM +/- 10% TOLERANCE" at 66.569,-10.979 h1.27
  text "6)ALL FABRICATION ITEM MUST MEET OR EXCEED BEST INDUSTRY PRACTICE. IPC-A-600C (Commercial Std.)" at 66.569,-13.21 h1.27
  text "7)MINIMUM COPPER WALL THICKNESS OF PLATED-THRU   HOLES TO BE 0.001 INCH, WITH A MINIMUM ANNULAR RING OF 0.002 INCH" at 66.569,-15.442 h1.27
  text "8)MAX. WARP & TWIST TO BE .0075 INCHES PER INCH" at 66.569,-17.673 h1.27
  text "9)HOLE POSITIONAL TOLERANCE ACCURACY IS  +/- 3 MILS" at 66.569,-19.904 h1.27
  text "10)SOLDERMASK BOTH SIDES PER ARTWORK.GREEN LPI" at 66.569,-22.135 h1.27
  text "11)SILKSCREEN BOTH SIDES PER ARTWORK.COLOR=WHITE." at 66.569,-24.163 h1.27
  text ".layer_name" at 10.815,-41.172 h1.52
M11 Gerber Information:
  circle w0.254: c88.215,-48.168 r1.3
  region: 87.741,-40.931 72.213,-40.931 71.519,-42.707 70.308,-43.932 68.911,-42.072 68.911,-40.421 70.054,-39.024 71.49,-38.645 87.741,-38.645
  region: 73.737,-49.261 62.981,-49.261 63.975,-46.768 71.832,-46.768 72.281,-46.009 74.49,-48.557
  lines w0.254: 63.975,-46.768 72.767,-46.768 69.701,-43.23 cw(c71.504,-41.286) 71.744,-38.645 88.508,-38.645 87.746,-40.931 ; 67.289,-38.398 cw(c69.715,-39.369) 69.951,-36.766 ; 67.328,-38.366 62.981,-49.261 82.304,-49.261 ccw(c82.553,-46.526) 85.102,-47.546 ; 69.067,-42.3 74.49,-48.557 ; 69.321,-42.3 74.626,-48.422 ; 69.321,-42.046 74.626,-48.168 ; 69.419,-40.931 82.412,-40.931 ; 69.448,-41.919 74.753,-48.041 ; 69.575,-41.792 74.88,-47.914 ; 69.702,-41.665 75.007,-47.787 ; 69.829,-41.538 75.134,-47.66 ; 69.884,-39.586 75.189,-45.707 ; 69.953,-36.766 89.402,-36.766 85.103,-47.544 ; 69.956,-41.411 75.207,-47.47 ; 69.956,-41.157 75.261,-47.279 ; 69.956,-40.903 75.261,-47.025 ; 69.956,-40.014 75.261,-46.136 ; 70.083,-40.776 75.388,-46.898 ; 70.083,-40.395 75.388,-46.517 ; 71.455,-46.781 ccw(c71.56,-46.246) 71.858,-45.789 ; 72.542,-40.918 ccw(c72.516,-41.485) 72.185,-41.947 74.55,-44.676 cw(c72.747,-46.62) 73.479,-49.169 ; 78.823,-49.057 81.712,-40.677 ; 79.045,-49.007 81.915,-40.686 ; 79.172,-49.007 82.042,-40.686 ; 79.426,-49.007 82.296,-40.686 ; 79.68,-49.007 82.55,-40.686 ; 79.934,-49.007 82.804,-40.686 ; 80.188,-49.007 83.058,-40.686 ; 80.442,-49.007 83.312,-40.686 ; 80.696,-49.007 83.566,-40.686 ; 80.95,-49.007 83.82,-40.686 ; 81.159,-49.057 84.048,-40.677 ; 84.048,-40.931 87.741,-40.931 ; 87.072,-40.929 87.834,-38.643 ; 87.238,-40.931 88,-38.645 ; 87.492,-40.931 88.254,-38.645
  lines w0.3: 1.211,-48.147 61.211,-48.147 ; 1.211,-43.147 61.211,-43.147 ; 1.211,-38.147 61.211,-38.147 ; 41.211,-53.147 41.211,-38.147 ; 61.211,-53.147 61.211,-33.147 ; 78.823,-49.057 81.159,-49.057 ; 1.212,-53.147 1.212,-33.147 91.211,-33.147 91.211,-53.147 1.211,-53.147
  text "Project: AUX STAGE BOARD" at 2.211,-36.363 h3
  text ".layer_name" at 9.421,-41.41 h1.52
  text "Layer:" at 2.212,-41.447 h3
  text "Variant: '.VariantName'" at 2.211,-46.447 h3
  text "R" at 87.707,-48.93 h1.52
  text "YEAR: 2022" at 2.211,-51.447 h3
  text "Rev: A" at 42.27,-51.447 h3
M12 Stackup:
  drawing of 197 lines, arcs and shapes, not listed
  text "Layer" at 76.107,37.922 h1.52
  text "Name" at 86.519,37.922 h1.52
  text "Material" at 110.134,37.922 h1.52
  text "Thickness" at 131.972,37.922 h1.52
  text "Constant" at 148.478,37.922 h1.52
  text "Board Layer Stack" at 162.953,37.922 h1.52
  text "Top Overlay" at 86.519,34.874 h1.52
  text "1oz(35um)" at 197.149,32.028 h1.52
  text "Top Solder" at 86.519,31.826 h1.52
  text "Solder Resist" at 110.134,31.826 h1.52
  text "0.40mil" at 131.972,31.826 h1.52
  text "3.5" at 148.478,31.826 h1.52
  text "1" at 76.107,28.778 h1.52
  text "Top Layer" at 86.519,28.778 h1.52
  text "1.38mil" at 131.972,28.778 h1.52
  text "Dielectric" at 86.519,25.73 h1.52
  text "FR-4 High TG" at 110.134,25.73 h1.52
  text "58.00mil" at 131.972,25.73 h1.52
  text "4.2" at 148.478,25.73 h1.52
  text "2" at 76.107,22.682 h1.52
  text "Bottom Layer" at 86.519,22.682 h1.52
  text "1.38mil" at 131.972,22.682 h1.52
  text "1oz(35um)" at 196.895,22.503 h1.52
  text "Bottom Solder" at 86.519,19.634 h1.52
  text "Solder Resist" at 110.134,19.634 h1.52
  text "0.40mil" at 131.972,19.634 h1.52
  text "3.5" at 148.478,19.634 h1.52
  text "Bottom Overlay" at 86.519,16.586 h1.52
  text "COPPER THICKNESS: FINISHED" at 74.329,13.657 h1.02
  text ".layer_name" at 11.339,-40.776 h1.52
Drill Drawing:
  drawing of 191 lines, arcs and shapes, not listed
  text "PCB SPECIFICATIONS :" at -1.515,125.023 h3
  text "A.   MATERIAL :" at -1.515,121.023 h3
  text "FR-4 HIGH TG" at 36.985,121.023 h3
  text "B.   MATERIAL FAMILY :" at -1.515,118.023 h3
  text "N/A" at 36.985,118.023 h3
  text "x   GREEN" at 37.186,115.256 h3
  text "WHITE" at 56.914,115.075 h3
  text "C.   SOLDERMASK COLOR :" at -1.515,115.023 h3
  text "BLUE" at 71.735,115.023 h3
  text "BLACK" at 87.735,115.023 h3
  text "D.   SILKSCREEN COLOR :" at -1.515,112.023 h3
  text "X  WHITE" at 36.985,112.023 h3
  text "YELLOW" at 53.485,112.023 h3
  text "BLACK" at 71.735,112.023 h3
  text "Blue ink PANTONE 2955" at 87.735,112.023 h3
  text "E.   SURFACE FINISH :" at -1.515,109.023 h3
  text "X  ENIG" at 36.985,109.023 h3
  text "IMMERSION SILVER" at 53.485,109.023 h3
  text "IMMERSION TIN" at 87.735,109.023 h3
  text "HASL" at 36.985,106.023 h3
  text "HASL (PB-FREE)" at 53.485,106.023 h3
  text "GOLDEN FINGER" at 87.735,106.023 h3
  text "MINIMUM PARAMETERS" at 145.972,105.58 h3
  text "F.   IMPEDANCE CONTROL :" at -1.515,103.023 h3
  text "X  NO" at 36.985,103.023 h3
  text "YES  (SEE IMPEDANCE TABLE FOR DETAIL INFORMATION)" at 53.485,103.023 h3
  text "DEFAULT" at 145.972,100.08 h3
  text "G.   VIA TENTING :" at -1.515,100.023 h3
  text "YES" at 56.49,99.787 h3
  text "X  NO" at 37.087,99.645 h3
  text "TRACKS : 0.508mm           /  GAPS     : 0.229mm" at 145.972,94.33 h3
  text "H.   STACK-UP :" at -1.515,94.023 h3
  text "SEE LAYER STACK-UP SEQUENCE FOR OVERALL THICKNESS." at 36.985,94.023 h3
  text "Symbol" at 76.596,81.636 h1.83
  text "Count" at 89.445,81.636 h1.83
  text "Hole Size" at 103.158,81.636 h1.83
  text "Plated" at 132.359,81.636 h1.83
  text "Via/Pad" at 145.209,81.636 h1.83
  text "1" at 89.445,77.826 h1.52
  text "35.43mil (0.900mm)" at 103.158,77.826 h1.52
  text "NPTH" at 132.359,77.826 h1.52
  text "Pad" at 145.209,77.826 h1.52
  text "1" at 89.445,74.016 h1.52
  text "51.18mil (1.300mm)" at 103.158,74.016 h1.52
  text "PTH" at 132.359,74.016 h1.52
  text "Pad" at 145.209,74.016 h1.52
  text "2" at 89.445,70.206 h1.52
  text "52.00mil (1.321mm)" at 103.158,70.206 h1.52
  text "PTH" at 132.359,70.206 h1.52
  text "Pad" at 145.209,70.206 h1.52
  text "2" at 89.445,66.396 h1.52
  text "145.67mil (3.700mm)" at 103.158,66.396 h1.52
  text "PTH" at 132.359,66.396 h1.52
  text "Pad" at 145.209,66.396 h1.52
  text "4" at 89.445,62.586 h1.52
  text "31.50mil (0.800mm)" at 103.158,62.586 h1.52
  text "PTH" at 132.359,62.586 h1.52
  text "Pad" at 145.209,62.586 h1.52
  text "10" at 89.445,58.776 h1.52
  text "34.00mil (0.864mm)" at 103.158,58.776 h1.52
  text "PTH" at 132.359,58.776 h1.52
  text "Pad" at 145.209,58.776 h1.52
  text "10" at 89.445,54.966 h1.52
  text "39.37mil (1.000mm)" at 103.158,54.966 h1.52
  text "PTH" at 132.359,54.966 h1.52
  text "Pad" at 145.209,54.966 h1.52
  text "21" at 89.445,51.156 h1.52
  text "35.43mil (0.900mm)" at 103.158,51.156 h1.52
  text "PTH" at 132.359,51.156 h1.52
  text "Pad" at 145.209,51.156 h1.52
  text "DRILL TOLERANCE:" at 162.699,51.156 h1.52
  text "FOR 16MIL DRILL +0/-16MIL" at 162.859,47.839 h1.52
  text "31" at 89.445,47.346 h1.52
  text "16.00mil (0.406mm)" at 103.158,47.346 h1.52
  text "PTH" at 132.359,47.346 h1.52
  text "Via" at 145.209,47.346 h1.52
  text "FOR PTH DRILL +/-3MIL" at 162.859,44.842 h1.52
  text "82 Total" at 89.445,43.536 h1.52
  text "FOR NPTH DRILL +/-2MIL" at 162.859,42.266 h1.52
  text ".layer_name" at 10.846,-41.003 h1.52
